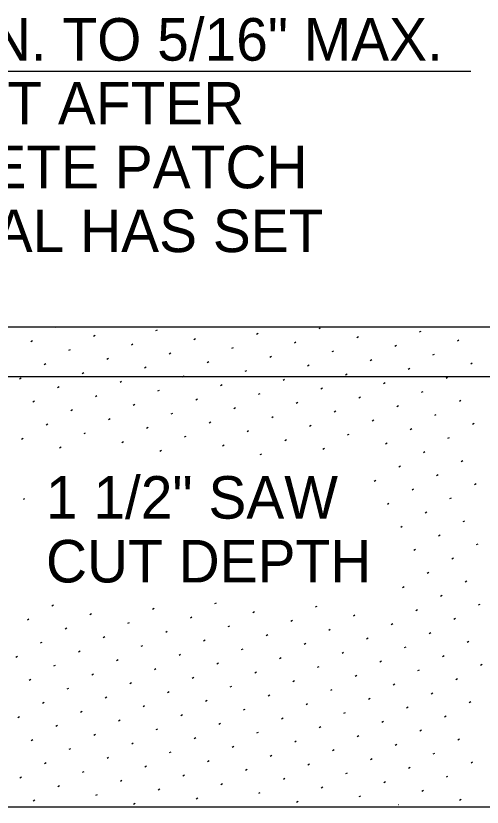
# Model space of a CAD drawing. Extents: x 99862 to 104211, y 98939 to 105076.
# Drawn here: x 101508.7 to 101684.2, y 104082.9 to 104380.5 of the extents above; entities that cross this region are included whole.
import ezdxf

# ---------------------------------------------------------------- set-up
doc = ezdxf.new("R2010")
doc.units = 0
for name, color, linetype in [('Level 1', 7, 'Continuous'), ('Level 15', 7, 'Continuous'), ('Level 2', 7, 'Continuous'), ('Level 20', 7, 'Continuous'), ('Level 3', 7, 'Continuous'), ('Level 6', 7, 'Continuous')]:
    doc.layers.add(name, color=color, linetype=linetype)

msp = doc.modelspace()

# ---------------------------------------------------------------- linework, layer by layer
at = {"layer": 'Level 1'}
msp.add_line((101394.64, 104263.53), (102106.49, 104263.53), dxfattribs=at)
at = {"layer": 'Level 15'}
msp.add_line((101394.48, 104359.62), (101680, 104359.62), dxfattribs=at)
at = {"layer": 'Level 2'}
msp.add_line((101899.72, 104082.86), (101399.29, 104082.86), dxfattribs=at)
at = {"layer": 'Level 3'}
for p, q in [((101523.67, 104263.34), (101524, 104263.53)), ((101561.48, 104262.07), (101562.08, 104262.42)), ((101622.82, 104262.84), (101623.42, 104263.19)), ((101537.94, 104260.03), (101538.55, 104260.38)), ((101599.28, 104260.8), (101599.89, 104261.15)), ((101637.08, 104259.53), (101637.69, 104259.88)), ((101660.62, 104261.58), (101661.22, 104261.93)), ((101514.41, 104257.99), (101515.01, 104258.34)), ((101552.21, 104256.72), (101552.82, 104257.07)), ((101575.74, 104258.76), (101576.35, 104259.11)), ((101613.55, 104257.49), (101614.15, 104257.84)), ((101651.35, 104256.22), (101651.96, 104256.57)), ((101674.89, 104258.27), (101675.49, 104258.62)), ((101528.67, 104254.68), (101529.28, 104255.03)), ((101566.48, 104253.41), (101567.08, 104253.76)), ((101590.01, 104255.45), (101590.62, 104255.8)), ((101627.82, 104254.18), (101628.42, 104254.53)), ((101542.94, 104251.37), (101543.55, 104251.72)), ((101580.74, 104250.1), (101581.35, 104250.45)), ((101604.28, 104252.14), (101604.89, 104252.49)), ((101642.08, 104250.87), (101642.69, 104251.22)), ((101665.62, 104252.92), (101666.22, 104253.27)), ((101519.41, 104249.33), (101520.01, 104249.68)), ((101557.21, 104248.06), (101557.82, 104248.41)), ((101618.55, 104248.83), (101619.15, 104249.18)), ((101656.35, 104247.56), (101656.96, 104247.91)), ((101679.89, 104249.61), (101680.49, 104249.96)), ((101533.67, 104246.02), (101534.28, 104246.37)), ((101571.48, 104244.75), (101572.08, 104245.1)), ((101595.01, 104246.79), (101595.62, 104247.14)), ((101632.82, 104245.52), (101633.42, 104245.87)), ((101670.62, 104244.25), (101671.22, 104244.6)), ((101510.14, 104243.98), (101510.74, 104244.33)), ((101547.94, 104242.71), (101548.55, 104243.06)), ((101585.74, 104241.44), (101586.35, 104241.79)), ((101609.28, 104243.48), (101609.89, 104243.83)), ((101647.08, 104242.21), (101647.69, 104242.56)), ((101524.41, 104240.67), (101525.01, 104241.02)), ((101562.21, 104239.4), (101562.82, 104239.75)), ((101600.01, 104238.13), (101600.62, 104238.48)), ((101623.55, 104240.17), (101624.15, 104240.52)), ((101661.35, 104238.9), (101661.96, 104239.25)), ((101515.14, 104235.32), (101515.74, 104235.67)), ((101538.67, 104237.36), (101539.28, 104237.71)), ((101576.48, 104236.09), (101577.08, 104236.44)), ((101637.82, 104236.86), (101638.42, 104237.21)), ((101675.62, 104235.59), (101676.22, 104235.94)), ((101552.94, 104234.05), (101553.55, 104234.4)), ((101590.74, 104232.78), (101591.35, 104233.13)), ((101614.28, 104234.82), (101614.89, 104235.17)), ((101652.08, 104233.55), (101652.69, 104233.9)), ((101529.41, 104232.01), (101530.01, 104232.36)), ((101567.21, 104230.74), (101567.82, 104231.09)), ((101605.01, 104229.47), (101605.62, 104229.82)), ((101628.55, 104231.51), (101629.15, 104231.86)), ((101666.35, 104230.24), (101666.96, 104230.59)), ((101520.14, 104226.66), (101520.74, 104227.01)), ((101543.67, 104228.7), (101544.28, 104229.05)), ((101581.48, 104227.43), (101582.08, 104227.78)), ((101642.82, 104228.2), (101643.42, 104228.55)), ((101680.62, 104226.93), (101681.22, 104227.28)), ((101534.41, 104223.35), (101535.01, 104223.7)), ((101557.94, 104225.39), (101558.55, 104225.74)), ((101595.74, 104224.12), (101596.35, 104224.47)), ((101619.28, 104226.16), (101619.89, 104226.51)), ((101657.08, 104224.89), (101657.69, 104225.24)), ((101510.87, 104221.31), (101511.48, 104221.66)), ((101572.21, 104222.08), (101572.82, 104222.43)), ((101610.01, 104220.81), (101610.62, 104221.16)), ((101633.55, 104222.85), (101634.15, 104223.2)), ((101671.35, 104221.58), (101671.96, 104221.93)), ((101525.14, 104218), (101525.74, 104218.35)), ((101548.67, 104220.04), (101549.28, 104220.39)), ((101586.48, 104218.77), (101587.08, 104219.12)), ((101624.28, 104217.5), (101624.89, 104217.85)), ((101647.82, 104219.54), (101648.42, 104219.89)), ((101562.94, 104216.73), (101563.55, 104217.08)), ((101600.74, 104215.46), (101601.35, 104215.81)), ((101662.08, 104216.23), (101662.69, 104216.58)), ((101676.35, 104212.92), (101676.96, 104213.27)), ((101652.82, 104210.88), (101653.42, 104211.23)), ((101643.55, 104205.53), (101644.15, 104205.88)), ((101667.08, 104207.57), (101667.69, 104207.92)), ((101681.35, 104204.26), (101681.96, 104204.61)), ((101657.82, 104202.22), (101658.42, 104202.57)), ((101511.6, 104198.64), (101512.08, 104198.91)), ((101648.55, 104196.87), (101649.15, 104197.22)), ((101672.08, 104198.91), (101672.69, 104199.26)), ((101662.82, 104193.56), (101663.42, 104193.91)), ((101653.55, 104188.21), (101654.15, 104188.56)), ((101677.08, 104190.25), (101677.69, 104190.6)), ((101667.82, 104184.9), (101668.42, 104185.25)), ((101682.08, 104181.59), (101682.69, 104181.94)), ((101658.55, 104179.55), (101659.15, 104179.9)), ((101672.82, 104176.24), (101673.42, 104176.59)), ((101663.55, 104170.89), (101664.15, 104171.24)), ((101677.82, 104167.58), (101678.42, 104167.93)), ((101654.28, 104165.54), (101654.89, 104165.89)), ((101668.55, 104162.23), (101669.15, 104162.58)), ((101522.34, 104158.64), (101522.94, 104158.99)), ((101583.67, 104159.42), (101584.28, 104159.77)), ((101621.48, 104158.15), (101622.08, 104158.5)), ((101682.82, 104158.92), (101683.42, 104159.27)), ((101536.6, 104155.33), (101537.21, 104155.68)), ((101560.14, 104157.38), (101560.74, 104157.73)), ((101597.94, 104156.11), (101598.55, 104156.46)), ((101635.74, 104154.84), (101636.35, 104155.19)), ((101659.28, 104156.88), (101659.89, 104157.23)), ((101513.07, 104153.29), (101513.67, 104153.64)), ((101550.87, 104152.02), (101551.48, 104152.37)), ((101574.41, 104154.07), (101575.01, 104154.42)), ((101612.21, 104152.8), (101612.82, 104153.15)), ((101673.55, 104153.57), (101674.15, 104153.92)), ((101527.34, 104149.98), (101527.94, 104150.33)), ((101588.67, 104150.76), (101589.28, 104151.11)), ((101626.48, 104149.49), (101627.08, 104149.84)), ((101650.01, 104151.53), (101650.62, 104151.88)), ((101541.6, 104146.67), (101542.21, 104147.02)), ((101565.14, 104148.71), (101565.74, 104149.06)), ((101602.94, 104147.45), (101603.55, 104147.8)), ((101640.74, 104146.18), (101641.35, 104146.53)), ((101664.28, 104148.22), (101664.89, 104148.57)), ((101518.07, 104144.63), (101518.67, 104144.98)), ((101555.87, 104143.36), (101556.48, 104143.71)), ((101579.41, 104145.41), (101580.01, 104145.76)), ((101617.21, 104144.14), (101617.82, 104144.49)), ((101678.55, 104144.91), (101679.15, 104145.26)), ((101532.34, 104141.32), (101532.94, 104141.67)), ((101570.14, 104140.05), (101570.74, 104140.4)), ((101593.67, 104142.1), (101594.28, 104142.45)), ((101631.48, 104140.83), (101632.08, 104141.18)), ((101655.01, 104142.87), (101655.62, 104143.22)), ((101508.8, 104139.28), (101509.41, 104139.63)), ((101546.6, 104138.01), (101547.21, 104138.36)), ((101607.94, 104138.79), (101608.55, 104139.14)), ((101645.74, 104137.52), (101646.35, 104137.87)), ((101669.28, 104139.56), (101669.89, 104139.91)), ((101523.07, 104135.97), (101523.67, 104136.32)), ((101560.87, 104134.7), (101561.48, 104135.05)), ((101584.41, 104136.75), (101585.01, 104137.1)), ((101622.21, 104135.48), (101622.82, 104135.83)), ((101660.01, 104134.21), (101660.62, 104134.56)), ((101683.55, 104136.25), (101684.15, 104136.6)), ((101537.34, 104132.66), (101537.94, 104133.01)), ((101575.14, 104131.39), (101575.74, 104131.74)), ((101598.67, 104133.44), (101599.28, 104133.79)), ((101636.48, 104132.17), (101637.08, 104132.52)), ((101513.8, 104130.62), (101514.41, 104130.97)), ((101551.6, 104129.35), (101552.21, 104129.7)), ((101589.41, 104128.08), (101590.01, 104128.43)), ((101612.94, 104130.13), (101613.55, 104130.48)), ((101650.74, 104128.86), (101651.35, 104129.21)), ((101674.28, 104130.9), (101674.89, 104131.25)), ((101528.07, 104127.31), (101528.67, 104127.66)), ((101565.87, 104126.04), (101566.48, 104126.39)), ((101627.21, 104126.82), (101627.82, 104127.17)), ((101665.01, 104125.55), (101665.62, 104125.9)), ((101542.34, 104124), (101542.94, 104124.35)), ((101580.14, 104122.73), (101580.74, 104123.08)), ((101603.67, 104124.78), (101604.28, 104125.13)), ((101641.48, 104123.51), (101642.08, 104123.86)), ((101679.28, 104122.24), (101679.89, 104122.59)), ((101518.8, 104121.96), (101519.41, 104122.31)), ((101556.6, 104120.69), (101557.21, 104121.04)), ((101594.41, 104119.42), (101595.01, 104119.77)), ((101617.94, 104121.47), (101618.55, 104121.82)), ((101655.74, 104120.2), (101656.35, 104120.55)), ((101509.53, 104116.61), (101510.14, 104116.96)), ((101533.07, 104118.65), (101533.67, 104119)), ((101570.87, 104117.38), (101571.48, 104117.73)), ((101608.67, 104116.12), (101609.28, 104116.47)), ((101632.21, 104118.16), (101632.82, 104118.51)), ((101670.01, 104116.89), (101670.62, 104117.24)), ((101523.8, 104113.3), (101524.41, 104113.65)), ((101547.34, 104115.34), (101547.94, 104115.69)), ((101585.14, 104114.07), (101585.74, 104114.42)), ((101646.48, 104114.85), (101647.08, 104115.2)), ((101561.6, 104112.03), (101562.21, 104112.38)), ((101599.41, 104110.76), (101600.01, 104111.11)), ((101622.94, 104112.81), (101623.55, 104113.16)), ((101660.74, 104111.54), (101661.35, 104111.89)), ((101514.53, 104107.95), (101515.14, 104108.3)), ((101538.07, 104109.99), (101538.67, 104110.34)), ((101575.87, 104108.72), (101576.48, 104109.07)), ((101613.67, 104107.45), (101614.28, 104107.8)), ((101637.21, 104109.5), (101637.82, 104109.85)), ((101675.01, 104108.23), (101675.62, 104108.58)), ((101528.8, 104104.64), (101529.41, 104104.99)), ((101552.34, 104106.68), (101552.94, 104107.03)), ((101590.14, 104105.41), (101590.74, 104105.76)), ((101651.48, 104106.19), (101652.08, 104106.54)), ((101543.07, 104101.33), (101543.67, 104101.68)), ((101566.6, 104103.37), (101567.21, 104103.72)), ((101604.41, 104102.1), (101605.01, 104102.45)), ((101627.94, 104104.15), (101628.55, 104104.5)), ((101665.74, 104102.88), (101666.35, 104103.23)), ((101519.53, 104099.29), (101520.14, 104099.64)), ((101580.87, 104100.06), (101581.48, 104100.41)), ((101618.67, 104098.79), (101619.28, 104099.14)), ((101642.21, 104100.84), (101642.82, 104101.19)), ((101680.01, 104099.57), (101680.62, 104099.92)), ((101533.8, 104095.98), (101534.41, 104096.33)), ((101557.34, 104098.02), (101557.94, 104098.37)), ((101595.14, 104096.75), (101595.74, 104097.1)), ((101632.94, 104095.49), (101633.55, 104095.84)), ((101656.48, 104097.53), (101657.08, 104097.88)), ((101510.26, 104093.94), (101510.87, 104094.29)), ((101548.07, 104092.67), (101548.67, 104093.02)), ((101571.6, 104094.71), (101572.21, 104095.06)), ((101609.41, 104093.44), (101610.01, 104093.79)), ((101670.74, 104094.22), (101671.35, 104094.57)), ((101524.53, 104090.63), (101525.14, 104090.98)), ((101562.34, 104089.36), (101562.94, 104089.71)), ((101585.87, 104091.4), (101586.48, 104091.75)), ((101623.67, 104090.13), (101624.28, 104090.48)), ((101647.21, 104092.18), (101647.82, 104092.53)), ((101538.8, 104087.32), (101539.41, 104087.67)), ((101600.14, 104088.09), (101600.74, 104088.44)), ((101637.94, 104086.82), (101638.55, 104087.17)), ((101661.48, 104088.87), (101662.08, 104089.22)), ((101515.26, 104085.28), (101515.87, 104085.63)), ((101553.07, 104084.01), (101553.67, 104084.36)), ((101576.6, 104086.05), (101577.21, 104086.4)), ((101614.41, 104084.78), (101615.01, 104085.13)), ((101652.79, 104083.85), (101652.82, 104083.87)), ((101675.74, 104085.56), (101676.35, 104085.91))]:
    msp.add_line(p, q, dxfattribs=at)
at = {"layer": 'Level 6'}
msp.add_line((102647.84, 104244.65), (101394.64, 104244.65), dxfattribs=at)

# ---------------------------------------------------------------- texts
at = {"layer": 'Level 20'}
for s, p in [('3/16" MIN. TO 5/16" MAX. ', (101419.98, 104363.62)), ('SAW CUT AFTER ', (101419.98, 104339.62)), ('CONCRETE PATCH ', (101419.98, 104315.62)), ('MATERIAL HAS SET', (101419.98, 104291.62)), ('1 1/2" SAW', (101520.08, 104191.37)), ('CUT DEPTH', (101520.08, 104167.37))]:
    msp.add_text(s, height=16, dxfattribs=at).set_placement(p)

doc.saveas('drawing.dxf')
